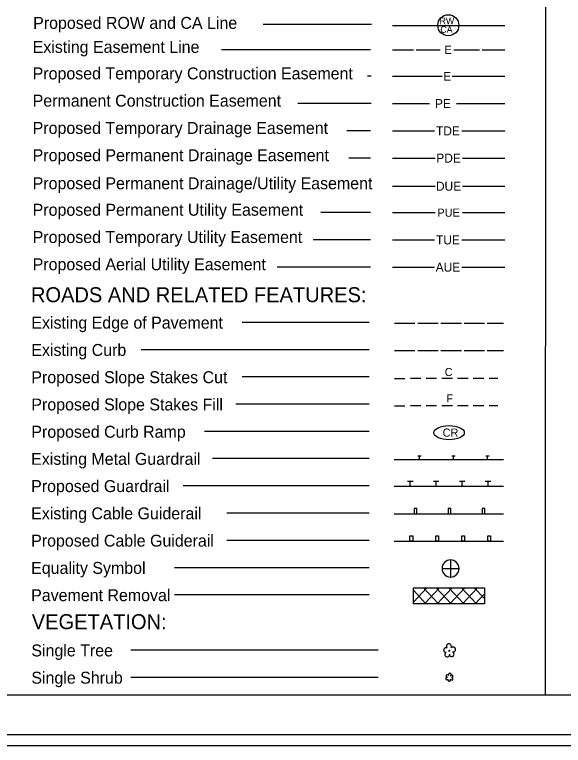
# Model space of a CAD drawing. Extents: x 811137 to 813186, y 647386 to 648494.
# Drawn here: x 811598 to 812004, y 647386 to 647927 of the extents above; entities that cross this region are included whole.
import ezdxf

# ---------------------------------------------------------------- set-up
doc = ezdxf.new("R2010")
doc.units = 0
for name, color, linetype in [('Default', 7, 'Continuous'), ('P_RDY_Easement_Permanent', 7, 'Continuous'), ('P_RDY_Easement_Permanent_Drainage_Utility', 7, 'Continuous'), ('P_RDY_WCC_CELL', 7, 'Continuous'), ('Sheet_Plan', 7, 'Continuous'), ('Sheet_Symbology', 7, 'Continuous'), ('z - Construction', 7, 'Continuous')]:
    doc.layers.add(name, color=color, linetype=linetype)

msp = doc.modelspace()

# ---------------------------------------------------------------- linework, layer by layer
at = {"layer": 'Default'}
msp.add_lwpolyline([(812820.63, 648494.02), (811136.63, 648494.02), (811136.63, 647394.02), (812820.63, 647394.02)], close=True, dxfattribs=at)
at = {"layer": 'P_RDY_Easement_Permanent'}
for p, q in [((811877.65, 647861.04), (811905.13, 647861.04)), ((811925.11, 647861.04), (811952.59, 647861.04)), ((811952.59, 647861.04), (811960.88, 647861.04))]:
    msp.add_line(p, q, dxfattribs=at)
at = {"layer": 'P_RDY_Easement_Permanent_Drainage_Utility'}
for p, q in [((811877.65, 647799.92), (811909.23, 647799.92)), ((811929.41, 647799.92), (811960.88, 647799.92))]:
    msp.add_line(p, q, dxfattribs=at)
at = {"layer": 'P_RDY_WCC_CELL'}
msp.add_ellipse((811919.52, 647617.48), major_axis=(11.31, 0), ratio=0.462467, dxfattribs=at)
at = {"layer": 'Sheet_Plan'}
msp.add_line((811178.28, 647423.58), (812803.25, 647423.58), dxfattribs=at)
at = {"layer": 'Sheet_Symbology'}
for p, q in [((811862.11, 647919.63), (811782.04, 647919.63)), ((811877.66, 647918.85), (811960.89, 647918.85)), ((811861.47, 647900.84), (811751.25, 647900.84)), ((811877.65, 647900.84), (811893.3, 647900.84)), ((811895.32, 647900.84), (811912.97, 647900.84)), ((811923.06, 647900.84), (811941.98, 647900.84)), ((811944, 647900.84), (811960.88, 647900.84)), ((811861.86, 647881.22), (811859.32, 647881.22)), ((811877.65, 647881.22), (811880.28, 647881.22)), ((811880.28, 647881.22), (811914.33, 647881.22)), ((811921.9, 647881.22), (811955.95, 647881.22)), ((811955.95, 647881.22), (811960.88, 647881.22)), ((811861.86, 647861.04), (811807.57, 647861.04)), ((811861.47, 647840.86), (811843.82, 647840.86)), ((811877.65, 647840.86), (811881.03, 647840.86)), ((811881.03, 647840.86), (811908.77, 647840.86)), ((811928.95, 647840.86), (811956.7, 647840.86)), ((811956.7, 647840.86), (811960.88, 647840.86)), ((811861.47, 647820.68), (811845.32, 647820.68)), ((811877.65, 647820.68), (811881.48, 647820.68)), ((811881.48, 647820.68), (811909.23, 647820.68)), ((811929.41, 647820.68), (811957.15, 647820.68)), ((811957.15, 647820.68), (811960.88, 647820.68)), ((811861.47, 647780.31), (811824.74, 647780.31)), ((811877.65, 647780.31), (811881.52, 647780.31)), ((811881.52, 647780.31), (811909.26, 647780.31)), ((811929.44, 647780.31), (811957.19, 647780.31)), ((811957.19, 647780.31), (811960.88, 647780.31)), ((811861.47, 647760.14), (811818.96, 647760.14)), ((811877.65, 647760.14), (811881.03, 647760.14)), ((811881.03, 647760.14), (811908.77, 647760.14)), ((811928.95, 647760.14), (811956.7, 647760.14)), ((811956.7, 647760.14), (811960.88, 647760.14)), ((811861.47, 647739.96), (811792.41, 647739.96)), ((811877.65, 647739.96), (811881.03, 647739.96)), ((811881.03, 647739.96), (811908.77, 647739.96)), ((811928.95, 647739.96), (811956.7, 647739.96)), ((811956.7, 647739.96), (811960.88, 647739.96)), ((811860.5, 647699.07), (811766.43, 647699.07)), ((811879.2, 647698.49), (811894.33, 647698.49)), ((811896.35, 647698.49), (811911.48, 647698.49)), ((811913.5, 647698.49), (811928.64, 647698.49)), ((811930.65, 647698.49), (811945.79, 647698.49)), ((811947.81, 647698.49), (811959.91, 647698.49)), ((811860.5, 647678.89), (811691.86, 647678.89)), ((811879.2, 647678.31), (811894.33, 647678.31)), ((811896.35, 647678.31), (811911.48, 647678.31)), ((811913.5, 647678.31), (811928.64, 647678.31)), ((811930.65, 647678.31), (811945.79, 647678.31)), ((811947.81, 647678.31), (811959.91, 647678.31)), ((811860.5, 647658.71), (811766.48, 647658.71)), ((811879.2, 647657.65), (811886.87, 647657.65)), ((811898.67, 647657.65), (811891.05, 647657.65)), ((811910.27, 647657.65), (811902.61, 647657.65)), ((811922.13, 647657.65), (811914.26, 647657.65)), ((811933.68, 647657.65), (811925.86, 647657.65)), ((811945.33, 647657.65), (811937.41, 647657.65)), ((811955.73, 647657.65), (811949.27, 647657.65)), ((811860.5, 647638.53), (811761.89, 647638.53)), ((811879.2, 647637.47), (811886.87, 647637.47)), ((811898.67, 647637.47), (811891.05, 647637.47)), ((811910.27, 647637.47), (811902.61, 647637.47)), ((811922.13, 647637.47), (811914.26, 647637.47)), ((811933.68, 647637.47), (811925.86, 647637.47)), ((811945.33, 647637.47), (811937.41, 647637.47)), ((811955.73, 647637.47), (811949.27, 647637.47)), ((811860.5, 647618.35), (811738.5, 647618.35)), ((811896.33, 647600.24), (811898.85, 647600.24)), ((811897.59, 647597.72), (811897.59, 647600.24)), ((811921.56, 647600.24), (811924.08, 647600.24)), ((811922.82, 647597.72), (811922.82, 647600.24)), ((811946.78, 647600.24), (811949.3, 647600.24)), ((811948.04, 647597.72), (811948.04, 647600.24)), ((811860.35, 647598.3), (811744.48, 647598.3)), ((811879.04, 647597.72), (811959.76, 647597.72)), ((811860.35, 647578.12), (811722.89, 647578.12)), ((811888.85, 647581.52), (811892.89, 647581.52)), ((811890.87, 647577.54), (811890.87, 647581.52)), ((811908.02, 647581.52), (811912.06, 647581.52)), ((811910.04, 647577.54), (811910.04, 647581.52)), ((811927.19, 647581.52), (811931.23, 647581.52)), ((811929.21, 647577.54), (811929.21, 647581.52)), ((811946.36, 647581.52), (811950.4, 647581.52)), ((811948.38, 647577.54), (811948.38, 647581.52)), ((811959.76, 647577.54), (811879.04, 647577.54)), ((811860.35, 647557.94), (811755.11, 647557.94)), ((811879.04, 647557.36), (811959.76, 647557.36)), ((811860.35, 647537.76), (811755.11, 647537.76)), ((811879.04, 647537.18), (811959.76, 647537.18)), ((811920.63, 647523.29), (811920.63, 647516.99)), ((811860.35, 647517.58), (811716.45, 647517.58)), ((811914.33, 647516.99), (811920.63, 647516.99)), ((811920.63, 647516.99), (811920.63, 647510.68)), ((811920.63, 647516.99), (811926.94, 647516.99)), ((811893.12, 647502.74), (811945.68, 647502.74)), ((811893.12, 647490.93), (811893.12, 647502.74)), ((811893.12, 647502.13), (811893.67, 647502.74)), ((811893.12, 647492.09), (811903.05, 647502.74)), ((811911.83, 647490.93), (811900.73, 647502.74)), ((811901.34, 647490.93), (811912.44, 647502.74)), ((811921.16, 647490.93), (811910.12, 647502.74)), ((811910.67, 647490.93), (811921.82, 647502.74)), ((811930.55, 647490.93), (811919.45, 647502.74)), ((811920.05, 647490.93), (811931.15, 647502.74)), ((811939.93, 647490.93), (811928.78, 647502.74)), ((811929.44, 647490.93), (811940.49, 647502.74)), ((811945.68, 647494.72), (811938.16, 647502.74)), ((811945.68, 647502.74), (811945.68, 647490.93)), ((811860.35, 647497.4), (811716.45, 647497.4)), ((811902.45, 647490.93), (811893.12, 647500.92)), ((811938.77, 647490.93), (811945.68, 647498.3)), ((811945.68, 647490.93), (811893.12, 647490.93)), ((811866.98, 647456.5), (811684.24, 647456.5)), ((811866.98, 647436.32), (811684.24, 647436.32))]:
    msp.add_line(p, q, dxfattribs=at)
for points in [[(811893.65, 647557.36), (811895.66, 647557.36), (811895.66, 647561.39), (811893.65, 647561.39)], [(811918.87, 647557.36), (811920.89, 647557.36), (811920.89, 647561.39), (811918.87, 647561.39)], [(811944.09, 647557.36), (811946.11, 647557.36), (811946.11, 647561.39), (811944.09, 647561.39)], [(811890.61, 647541.21), (811892.62, 647541.21), (811892.62, 647537.18), (811890.61, 647537.18)], [(811909.78, 647541.21), (811911.79, 647541.21), (811911.79, 647537.18), (811909.78, 647537.18)], [(811928.95, 647541.21), (811930.96, 647541.21), (811930.96, 647537.18), (811928.95, 647537.18)], [(811948.12, 647541.21), (811950.13, 647541.21), (811950.13, 647537.18), (811948.12, 647537.18)]]:
    msp.add_lwpolyline(points, close=True, dxfattribs=at)
for points in [[(811921, 647458.6), (811921.16, 647458.96), (811921.24, 647459.32), (811921.2, 647459.71), (811921.12, 647460.07), (811920.92, 647460.43), (811920.72, 647460.71), (811920.4, 647460.98), (811920.08, 647461.14), (811919.69, 647461.26), (811919.33, 647461.26), (811918.93, 647461.22), (811918.57, 647461.1), (811918.26, 647460.9), (811917.98, 647460.63), (811917.78, 647460.31), (811917.62, 647459.95), (811917.58, 647459.59), (811917.58, 647459.2), (811917.66, 647458.84), (811917.82, 647458.48), (811918.06, 647458.16), (811917.74, 647458.32), (811917.38, 647458.4), (811917.02, 647458.36), (811916.67, 647458.28), (811916.35, 647458.12), (811916.03, 647457.89), (811915.83, 647457.61), (811915.63, 647457.29), (811915.56, 647456.97), (811915.52, 647456.58), (811915.56, 647456.22), (811915.71, 647455.9), (811915.91, 647455.58), (811916.15, 647455.34), (811916.47, 647455.14), (811916.79, 647454.99), (811917.14, 647454.95), (811917.5, 647454.95), (811917.18, 647454.79), (811916.91, 647454.55), (811916.71, 647454.27), (811916.55, 647453.91), (811916.47, 647453.56), (811916.43, 647453.2), (811916.51, 647452.84), (811916.67, 647452.52), (811916.87, 647452.21), (811917.1, 647451.97), (811917.42, 647451.77), (811917.78, 647451.65), (811918.14, 647451.61), (811918.49, 647451.65), (811918.85, 647451.73), (811919.17, 647451.93), (811919.45, 647452.17), (811919.65, 647452.44), (811919.81, 647452.76), (811919.88, 647453.12)], [(811919.77, 647453.56), (811919.81, 647453.16), (811919.93, 647452.8), (811920.12, 647452.48), (811920.4, 647452.21), (811920.72, 647452.01), (811921.08, 647451.89), (811921.47, 647451.85), (811921.83, 647451.89), (811922.19, 647452.01), (811922.51, 647452.21), (811922.78, 647452.44), (811923.02, 647452.76), (811923.14, 647453.12), (811923.22, 647453.48), (811923.18, 647453.87), (811923.1, 647454.23), (811922.9, 647454.59), (811922.67, 647454.87), (811922.35, 647455.07), (811921.99, 647455.22), (811922.39, 647455.19), (811922.78, 647455.19), (811923.14, 647455.3), (811923.5, 647455.46), (811923.82, 647455.7), (811924.06, 647456.02), (811924.25, 647456.38), (811924.33, 647456.73), (811924.37, 647457.13), (811924.29, 647457.53), (811924.17, 647457.89), (811923.94, 647458.2), (811923.66, 647458.48), (811923.34, 647458.68), (811922.94, 647458.84), (811922.59, 647458.88), (811922.19, 647458.88), (811921.79, 647458.76), (811921.47, 647458.56), (811921.16, 647458.32)], [(811919.88, 647456.38), (811919.73, 647456.38), (811919.57, 647456.34), (811919.49, 647456.22), (811919.45, 647456.06), (811919.49, 647455.9), (811919.61, 647455.78), (811919.77, 647455.78), (811919.93, 647455.82), (811920.04, 647455.94), (811920.08, 647456.1), (811920, 647456.26), (811919.88, 647456.38)], [(811919.29, 647437.79), (811919.17, 647438.03), (811918.93, 647438.22), (811918.69, 647438.38), (811918.42, 647438.42), (811918.14, 647438.38), (811917.86, 647438.3), (811917.62, 647438.11), (811917.46, 647437.87), (811917.38, 647437.59), (811917.38, 647437.31), (811917.46, 647437.03), (811917.62, 647436.79), (811917.86, 647436.6), (811918.14, 647436.48), (811918.42, 647436.48), (811918.14, 647436.52), (811917.86, 647436.52), (811917.62, 647436.44), (811917.38, 647436.28), (811917.22, 647436.08), (811917.14, 647435.84), (811917.1, 647435.56), (811917.14, 647435.28), (811917.26, 647435.05), (811917.46, 647434.85), (811917.7, 647434.73), (811917.94, 647434.65), (811918.22, 647434.69), (811918.45, 647434.77), (811918.69, 647434.93), (811918.85, 647435.13), (811918.73, 647434.85), (811918.69, 647434.57), (811918.77, 647434.29), (811918.89, 647434.05), (811919.09, 647433.81), (811919.33, 647433.7), (811919.61, 647433.62), (811919.88, 647433.66), (811920.16, 647433.74), (811920.4, 647433.89), (811920.56, 647434.13), (811920.68, 647434.41), (811920.68, 647434.69), (811920.64, 647434.97), (811920.76, 647434.77), (811921, 647434.57), (811921.24, 647434.49), (811921.51, 647434.45), (811921.79, 647434.49), (811922.03, 647434.61), (811922.23, 647434.81), (811922.35, 647435.05), (811922.39, 647435.32), (811922.39, 647435.6), (811922.27, 647435.84), (811922.11, 647436.04), (811921.91, 647436.2), (811921.63, 647436.32), (811921.36, 647436.32), (811921.63, 647436.32), (811921.91, 647436.4), (811922.11, 647436.55), (811922.31, 647436.79), (811922.39, 647437.03), (811922.39, 647437.31), (811922.35, 647437.59), (811922.19, 647437.83), (811921.99, 647437.99), (811921.71, 647438.11), (811921.43, 647438.14), (811921.2, 647438.06), (811920.92, 647437.95), (811920.76, 647437.75), (811920.64, 647437.51)], [(811920.52, 647437.51), (811920.76, 647437.63), (811920.96, 647437.87), (811921.08, 647438.11), (811921.12, 647438.38), (811921.12, 647438.66), (811921, 647438.94), (811920.84, 647439.14), (811920.64, 647439.34), (811920.36, 647439.42), (811920.08, 647439.46), (811919.81, 647439.42), (811919.57, 647439.3), (811919.33, 647439.1), (811919.21, 647438.86), (811919.13, 647438.58), (811919.13, 647438.3), (811919.17, 647438.03), (811919.33, 647437.79)]]:
    msp.add_lwpolyline(points, dxfattribs=at)
msp.add_circle((811919.01, 647919), 7.79, dxfattribs=at)
for start, end in [(89.9944, 179.9989), (359.9944, 89.9989), (179.9944, 269.9989), (269.9944, 359.9989)]:
    msp.add_arc((811920.63, 647516.99), 6.31, start, end, dxfattribs=at)
at = {"layer": 'z - Construction'}
for p, q in [((811990.77, 648448.58), (811990.75, 647423.58)), ((811140.78, 647386.08), (812840.77, 647386.08))]:
    msp.add_line(p, q, dxfattribs=at)

# ---------------------------------------------------------------- texts
at = {"layer": 'P_RDY_Easement_Permanent_Drainage_Utility'}
msp.add_text('DUE', height=6.608, dxfattribs=at).set_placement((811909.83, 647796.59))
at = {"layer": 'P_RDY_WCC_CELL'}
msp.add_text('CR', height=6.054, dxfattribs=at).set_placement((811914.76, 647614.5))
at = {"layer": 'Sheet_Symbology'}
for s, height, p in [('Proposed ROW and CA Line', 8.8282, (811611.87, 647916.32)), ('RW', 4.882, (811912.51, 647919.78)), ('CA', 4.882, (811913.07, 647913.43)), ('Existing Easement Line', 8.8282, (811611.51, 647898.56)), ('E', 6.05, (811916.2, 647897.82)), ('Proposed Temporary Construction Easement', 8.8282, (811611.51, 647878.93)), ('E', 6.61, (811915.2, 647877.89)), ('Permanent Construction Easement', 8.8282, (811611.51, 647858.76)), ('PE', 6.608, (811909.1, 647857.71)), ('Proposed Temporary Drainage Easement', 8.8282, (811611.51, 647838.58)), ('TDE', 6.608, (811909.89, 647837.53)), ('Proposed Permanent Drainage Easement', 8.8282, (811611.51, 647818.4)), ('PDE', 6.608, (811910.09, 647817.35)), ('Proposed Permanent Drainage/Utility Easement', 8.8282, (811611.51, 647797.63)), ('Proposed Permanent Utility Easement', 8.8282, (811611.51, 647778.03)), ('PUE', 6.054, (811910.89, 647777.29)), ('Proposed Temporary Utility Easement', 8.8282, (811611.51, 647757.85)), ('TUE', 6.608, (811909.89, 647756.81)), ('Proposed Aerial Utility Easement', 8.8282, (811611.51, 647737.67)), ('AUE', 6.608, (811909.63, 647736.63)), ('ROADS AND RELATED FEATURES:', 11.0983, (811610.24, 647714.04)), ('Existing Edge of Pavement', 8.8282, (811610.54, 647694.48)), ('Existing Curb', 8.8282, (811610.54, 647674.3)), ('C', 5.98, (811916.33, 647659.4)), ('Proposed Slope Stakes Cut', 8.8282, (811610.54, 647654.12)), ('Proposed Slope Stakes Fill', 8.8282, (811610.54, 647633.94)), ('F', 5.98, (811917.54, 647639.86)), ('Proposed Curb Ramp', 8.8282, (811610.54, 647613.76)), ('Existing Metal Guardrail', 8.8282, (811610.38, 647593.7)), ('Proposed Guardrail', 8.8282, (811610.39, 647573.54)), ('Existing Cable Guiderail', 8.8282, (811610.39, 647553.36)), ('Proposed Cable Guiderail', 8.8282, (811610.39, 647533.18)), ('Equality Symbol', 8.8282, (811610.39, 647513)), ('Pavement Removal', 8.8282, (811610.39, 647492.82)), ('VEGETATION:', 11.0983, (811610.83, 647472.08)), ('Single Tree', 8.8282, (811610.55, 647451.93)), ('Single Shrub', 8.8282, (811610.55, 647431.75))]:
    msp.add_text(s, height=height, dxfattribs=at).set_placement(p)

doc.saveas('drawing.dxf')
